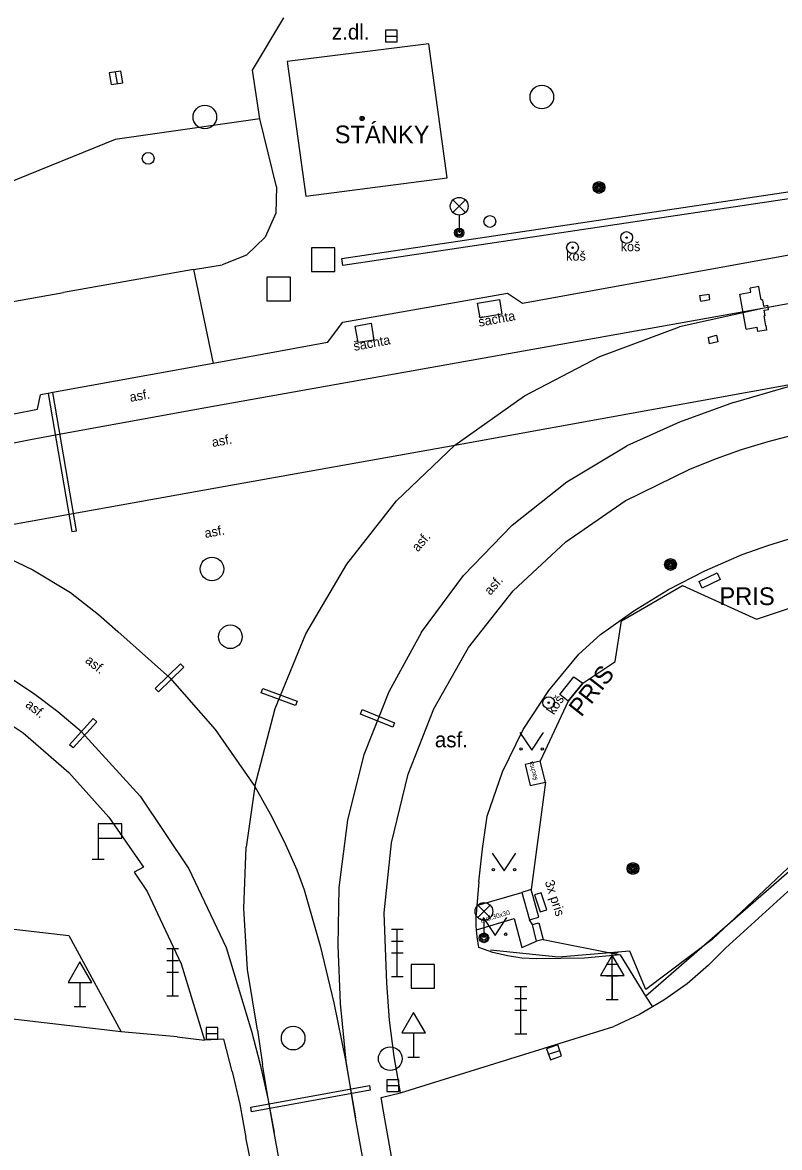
# Model space of a CAD drawing. Extents: x -600309 to -598967, y -1161267 to -1160292.
# Drawn here: x -599253.56 to -599221.51, y -1161223.69 to -1161176.07 of the extents above; entities that cross this region are included whole.
import ezdxf

# ---------------------------------------------------------------- set-up
doc = ezdxf.new("R2010")
doc.units = 0
for name, color, linetype in [('Level 10', 7, 'Continuous'), ('Level 11', 7, 'Continuous'), ('Level 13', 7, 'Continuous'), ('Level 23', 7, 'Continuous'), ('Level 24', 7, 'Continuous'), ('Level 25', 7, 'Continuous'), ('Level 26', 7, 'Continuous'), ('Level 27', 7, 'Continuous'), ('Level 28', 7, 'Continuous'), ('Level 33', 7, 'Continuous'), ('Level 34', 7, 'Continuous'), ('Level 36', 7, 'Continuous'), ('Level 39', 7, 'Continuous'), ('Level 40', 7, 'Continuous'), ('Level 41', 7, 'Continuous'), ('Level 42', 7, 'Continuous'), ('Level 5', 7, 'Continuous'), ('Level 9', 7, 'Continuous')]:
    doc.layers.add(name, color=color, linetype=linetype)

msp = doc.modelspace()

# ---------------------------------------------------------------- linework, layer by layer
at = {"layer": 'Level 10'}
for points in [[(-599243.51, -1161180.14), (-599243.82, -1161178.09), (-599242.49, -1161175.87)], [(-599243.51, -1161180.15), (-599249.64, -1161181.02), (-599254.23, -1161182.89)], [(-599232.39, -1161187.95), (-599216.66, -1161185.1)], [(-599240.64, -1161189.62), (-599239.99, -1161188.75), (-599233.02, -1161187.52), (-599232.39, -1161187.95)], [(-599240.64, -1161189.62), (-599245.49, -1161190.5)], [(-599245.49, -1161190.5), (-599252.28, -1161191.73), (-599252.48, -1161191.77), (-599252.8, -1161191.83)], [(-599225.3, -1161194.98), (-599224.21, -1161194.54), (-599223.11, -1161194.14), (-599221.98, -1161193.8), (-599220.85, -1161193.51)], [(-599234.68, -1161202.52), (-599232.78, -1161200.13), (-599230.55, -1161198.05), (-599228.04, -1161196.32), (-599225.3, -1161194.98)], [(-599238.14, -1161216.74), (-599238.24, -1161213.76), (-599237.94, -1161210.79), (-599237.23, -1161207.89), (-599236.14, -1161205.12), (-599234.68, -1161202.52)], [(-599255.66, -1161204.72), (-599253.54, -1161206.14), (-599251.6, -1161207.81), (-599249.9, -1161209.71), (-599248.44, -1161211.82)], [(-599248.44, -1161211.82), (-599248.83, -1161212.04)], [(-599248.83, -1161212.04), (-599248.29, -1161212.85), (-599246.84, -1161215.91), (-599245.86, -1161219.14)], [(-599223.79, -1161215.25), (-599220.07, -1161211.86)], [(-599224.51, -1161215.97), (-599223.79, -1161215.25)], [(-599249.38, -1161218.79), (-599256.77, -1161217.93), (-599271.44, -1161216.15)], [(-599224.51, -1161215.97), (-599225.42, -1161216.76), (-599226.4, -1161217.45), (-599226.88, -1161217.73), (-599227.43, -1161218.06), (-599228.52, -1161218.57)], [(-599237.56, -1161221.38), (-599237.83, -1161219.84), (-599238.02, -1161218.3), (-599238.14, -1161216.74)], [(-599247.01, -1161219.01), (-599249.38, -1161218.79)], [(-599237.56, -1161221.38), (-599228.52, -1161218.57)], [(-599247.01, -1161219.01), (-599245.86, -1161219.14)]]:
    msp.add_lwpolyline(points, dxfattribs=at)
at = {"layer": 'Level 11'}
for points in [[(-599242.81, -1161183.03), (-599243.51, -1161180.15), (-599243.51, -1161180.14)], [(-599242.81, -1161183.03), (-599242.83, -1161184.14), (-599243.28, -1161185.15), (-599244.08, -1161185.92), (-599245.11, -1161186.32)], [(-599246.32, -1161186.52), (-599245.11, -1161186.32)], [(-599246.32, -1161186.52), (-599251.83, -1161187.5)], [(-599246.32, -1161186.52), (-599245.49, -1161190.5)], [(-599222.38, -1161187.24), (-599222.75, -1161187.31)], [(-599222.72, -1161187.48), (-599222.75, -1161187.31)], [(-599222.35, -1161187.42), (-599222.38, -1161187.24)], [(-599285.55, -1161193.76), (-599281.38, -1161192.76), (-599251.83, -1161187.5)], [(-599224.88, -1161187.63), (-599224.49, -1161187.57)], [(-599224.83, -1161187.86), (-599224.88, -1161187.63)], [(-599224.83, -1161187.86), (-599224.45, -1161187.8)], [(-599224.45, -1161187.8), (-599224.49, -1161187.57)], [(-599223.19, -1161187.57), (-599222.72, -1161187.48)], [(-599222.92, -1161189.05), (-599223.19, -1161187.57)], [(-599222.28, -1161187.81), (-599222.35, -1161187.42)], [(-599222.23, -1161187.81), (-599222.28, -1161187.81)], [(-599222.23, -1161187.81), (-599222.18, -1161188.07)], [(-599222.18, -1161188.07), (-599222, -1161188.03)], [(-599222.15, -1161188.24), (-599221.97, -1161188.21)], [(-599222.11, -1161188.48), (-599222.15, -1161188.24)], [(-599221.97, -1161188.21), (-599222, -1161188.03)], [(-599222.11, -1161188.48), (-599222.16, -1161188.49)], [(-599222.08, -1161188.9), (-599222.09, -1161188.91), (-599222.16, -1161188.49)], [(-599222.92, -1161189.05), (-599222.47, -1161188.97)], [(-599222.47, -1161188.97), (-599222.44, -1161189.15)], [(-599222.05, -1161189.09), (-599222.44, -1161189.15)], [(-599222.08, -1161188.9), (-599222.05, -1161189.09)], [(-599224.53, -1161189.4), (-599224.17, -1161189.31)], [(-599224.53, -1161189.4), (-599224.48, -1161189.67)], [(-599224.12, -1161189.58), (-599224.48, -1161189.67)], [(-599224.17, -1161189.31), (-599224.12, -1161189.58)], [(-599252.93, -1161192.44), (-599252.8, -1161191.83)], [(-599262.96, -1161194.41), (-599252.93, -1161192.44)], [(-599223.08, -1161198.59), (-599222, -1161198.21), (-599220.91, -1161197.87), (-599219.8, -1161197.59), (-599218.68, -1161197.36)], [(-599229.09, -1161201.97), (-599227.68, -1161200.97), (-599226.2, -1161200.07), (-599224.67, -1161199.28), (-599223.08, -1161198.59)], [(-599230.01, -1161202.81), (-599229.09, -1161201.97)], [(-599233.88, -1161209.66), (-599233.23, -1161207.79), (-599232.36, -1161206), (-599231.28, -1161204.34), (-599230.01, -1161202.81)], [(-599227.18, -1161217.29), (-599220.44, -1161211.43), (-599216.22, -1161207.91)], [(-599234.24, -1161212.44), (-599234.08, -1161211.05), (-599233.88, -1161209.66)], [(-599234.24, -1161212.44), (-599234.32, -1161213.44), (-599234.35, -1161213.84)], [(-599234.32, -1161213.44), (-599232.42, -1161212.89)], [(-599257.7199, -1161214.01), (-599251.6, -1161214.7199), (-599249.38, -1161218.79)], [(-599234.24, -1161215.23), (-599234.31, -1161214.77), (-599234.34, -1161214.47), (-599234.35, -1161214.31), (-599234.35, -1161213.84)], [(-599234.34, -1161214.47), (-599232.74, -1161214), (-599232.41, -1161215.22), (-599231.8, -1161214.96)], [(-599231.97, -1161214.25), (-599232.09, -1161214.05)], [(-599231.78, -1161215.7), (-599232.41, -1161215.67), (-599233.03, -1161215.58), (-599233.64, -1161215.43), (-599234.24, -1161215.23)], [(-599228.25, -1161215.54), (-599229.77, -1161215.67), (-599231.78, -1161215.7)], [(-599228.25, -1161215.54), (-599227.18, -1161217.29)], [(-599227.18, -1161217.29), (-599226.88, -1161217.73)], [(-599244.68, -1161220.47), (-599245.04, -1161219.1), (-599245.86, -1161219.14)], [(-599244.68, -1161220.47), (-599244.36, -1161221.86), (-599244.1, -1161223.27)], [(-599236.75, -1161230.76), (-599238.26, -1161222.23), (-599238.38, -1161221.57), (-599237.56, -1161221.38)], [(-599242.28, -1161232.13), (-599244.1, -1161223.27)]]:
    msp.add_lwpolyline(points, dxfattribs=at)
at = {"layer": 'Level 13'}
for points in [[(-599176.03, -1161179.84), (-599185.38, -1161181.48), (-599211.11, -1161186.14), (-599222.22, -1161188.17), (-599231.95, -1161189.91), (-599245.73, -1161192.37), (-599252.16, -1161193.54), (-599253.22, -1161193.73), (-599269.67, -1161197)], [(-599254.02, -1161197.32), (-599251.59, -1161196.88), (-599245.38, -1161195.76), (-599235.26, -1161193.96), (-599218.74, -1161190.97), (-599212.41, -1161189.82), (-599183.76, -1161184.68), (-599173.82, -1161182.81)], [(-599222.22, -1161188.17), (-599225.74, -1161188.95)], [(-599235.26, -1161193.96), (-599232.31, -1161191.87), (-599229.12, -1161190.2), (-599225.74, -1161188.95)], [(-599223.46, -1161192.15), (-599221.12, -1161191.47), (-599218.74, -1161190.97)], [(-599223.46, -1161192.15), (-599225.74, -1161192.99)], [(-599225.74, -1161192.99), (-599227.97, -1161193.99)], [(-599243.72, -1161208.41), (-599242.86, -1161205.11), (-599241.56, -1161201.95), (-599239.83, -1161199), (-599237.72, -1161196.32), (-599235.26, -1161193.96)], [(-599236.66, -1161201.87), (-599234.89, -1161199.48), (-599232.83, -1161197.35), (-599230.51, -1161195.51), (-599227.97, -1161193.99)], [(-599256.29, -1161197.73), (-599253.12, -1161199.24), (-599251.53, -1161200.2), (-599250.35, -1161201.13), (-599249.52, -1161201.85)], [(-599268.01, -1161200.11), (-599266.08, -1161200.07), (-599263.89, -1161200.31), (-599261.69, -1161200.69), (-599259.15, -1161201.36), (-599257.24, -1161202.13), (-599255.3, -1161203.08), (-599254.18, -1161203.74), (-599253.1, -1161204.46), (-599252.06, -1161205.24), (-599251.07, -1161206.08)], [(-599249.52, -1161201.85), (-599247.33, -1161203.81), (-599245.4, -1161206), (-599243.73, -1161208.41)], [(-599240.15, -1161212.69), (-599239.79, -1161209.84), (-599239.09, -1161207.06), (-599238.03, -1161204.39), (-599236.65, -1161201.86)], [(-599251.07, -1161206.09), (-599248.58, -1161208.82), (-599246.52, -1161211.89), (-599244.94, -1161215.23)], [(-599243.73, -1161208.41), (-599244.09, -1161210.98)], [(-599243.72, -1161208.41), (-599243.07, -1161209.56)], [(-599243.07, -1161209.56), (-599242.48, -1161210.74), (-599241.95, -1161211.94)], [(-599243.61, -1161218.72), (-599244.03, -1161216.16), (-599244.19, -1161213.57), (-599244.09, -1161210.98)], [(-599241.95, -1161211.94), (-599241.63, -1161212.78)], [(-599241.63, -1161212.78), (-599240.96, -1161215.16), (-599240.38, -1161217.57), (-599239.88, -1161220), (-599239.46, -1161222.44)], [(-599239.46, -1161222.44), (-599239.85, -1161220.03), (-599240.1, -1161217.59), (-599240.2, -1161215.14), (-599240.15, -1161212.69)], [(-599244.94, -1161215.23), (-599243.87, -1161218.77)], [(-599243.87, -1161218.77), (-599243.5, -1161220.18), (-599243.17, -1161221.61), (-599242.9, -1161223.06)], [(-599243.61, -1161218.72), (-599243.4, -1161220.17)], [(-599242.9, -1161223.05), (-599243.16, -1161221.61), (-599243.4, -1161220.17)], [(-599238.11, -1161229.91), (-599239.46, -1161222.44)], [(-599241.55, -1161230.45), (-599242.9, -1161223.05)]]:
    msp.add_lwpolyline(points, dxfattribs=at)
at = {"layer": 'Level 23'}
for points in [[(-599225.61, -1161199.9), (-599222.48, -1161201.33), (-599202.67, -1161194.75), (-599197.63, -1161193.92), (-599196.7, -1161196.51)], [(-599228.2, -1161201.4), (-599225.61, -1161199.9)], [(-599228.46, -1161203.12), (-599228.2, -1161201.4)], [(-599230.45, -1161204.8), (-599229.84, -1161204.03), (-599228.52, -1161203.16), (-599228.46, -1161203.12)], [(-599230.45, -1161204.8), (-599231.64, -1161207.33)], [(-599231.42, -1161208.23), (-599232.02, -1161212.77)], [(-599231.52, -1161214.89), (-599228.25, -1161215.54)]]:
    msp.add_lwpolyline(points, dxfattribs=at)
at = {"layer": 'Level 24'}
for points in [[(-599240.04, -1161186.06), (-599216.7, -1161182.57)], [(-599216.66, -1161182.87), (-599240, -1161186.36)], [(-599240, -1161186.36), (-599240.04, -1161186.06)], [(-599251.27, -1161197.59), (-599252.28, -1161191.73), (-599252.48, -1161191.77)], [(-599252.48, -1161191.77), (-599251.47, -1161197.62)], [(-599251.47, -1161197.62), (-599251.27, -1161197.59)], [(-599224.91, -1161199.73), (-599224.15, -1161199.37)], [(-599224.78, -1161200.01), (-599224.91, -1161199.73)], [(-599224.02, -1161199.65), (-599224.78, -1161200.01)], [(-599224.15, -1161199.37), (-599224.02, -1161199.65)], [(-599247.94, -1161204.26), (-599246.87, -1161203.21)], [(-599246.73, -1161203.35), (-599247.81, -1161204.4)], [(-599246.87, -1161203.21), (-599246.73, -1161203.35)], [(-599230.81, -1161204.52), (-599230.22, -1161203.77)], [(-599229.84, -1161204.03), (-599230.45, -1161204.8)], [(-599230.22, -1161203.77), (-599229.84, -1161204.03)], [(-599247.81, -1161204.4), (-599247.94, -1161204.26)], [(-599243.45, -1161204.45), (-599243.39, -1161204.26)], [(-599242, -1161204.98), (-599243.45, -1161204.45)], [(-599243.39, -1161204.26), (-599241.93, -1161204.79)], [(-599230.45, -1161204.8), (-599230.81, -1161204.52)], [(-599241.93, -1161204.79), (-599242, -1161204.98)], [(-599239.25, -1161205.34), (-599239.18, -1161205.15)], [(-599237.88, -1161205.9), (-599239.25, -1161205.34)], [(-599239.18, -1161205.15), (-599237.81, -1161205.71)], [(-599251.57, -1161206.64), (-599250.57, -1161205.53)], [(-599250.42, -1161205.67), (-599251.42, -1161206.77)], [(-599250.57, -1161205.53), (-599250.42, -1161205.67)], [(-599237.81, -1161205.71), (-599237.88, -1161205.9)], [(-599251.42, -1161206.77), (-599251.57, -1161206.64)], [(-599231.6, -1161212.91), (-599231.88, -1161213)], [(-599231.88, -1161213), (-599231.64, -1161213.72)], [(-599231.36, -1161213.63), (-599231.6, -1161212.91)], [(-599231.64, -1161213.72), (-599231.36, -1161213.63)], [(-599243.9, -1161221.98), (-599238.87, -1161221.06)], [(-599238.87, -1161221.06), (-599238.84, -1161221.26)], [(-599238.84, -1161221.26), (-599243.87, -1161222.18)], [(-599243.87, -1161222.18), (-599243.9, -1161221.98)]]:
    msp.add_lwpolyline(points, dxfattribs=at)
at = {"layer": 'Level 25'}
for centre, radius in [((-599229.15, -1161183.05), 0.25), ((-599229.15, -1161183.05), 0.2), ((-599229.15, -1161183.05), 0.15), ((-599229.15, -1161183.05), 0.1), ((-599229.15, -1161183.05), 0.05), ((-599227.98, -1161185.17), 0.25), ((-599230.27, -1161185.6), 0.25), ((-599227.98, -1161185.17), 0.0303), ((-599230.27, -1161185.6), 0.0303), ((-599226.12, -1161199.01), 0.25), ((-599226.12, -1161199.01), 0.2), ((-599226.12, -1161199.01), 0.15), ((-599226.12, -1161199.01), 0.1), ((-599226.12, -1161199.01), 0.05), ((-599231.28, -1161204.86), 0.25), ((-599231.28, -1161204.86), 0.0303), ((-599227.71, -1161211.88), 0.25), ((-599227.71, -1161211.88), 0.2), ((-599227.71, -1161211.88), 0.15), ((-599227.71, -1161211.88), 0.1), ((-599227.71, -1161211.88), 0.05)]:
    msp.add_circle(centre, radius, dxfattribs=at)
at = {"layer": 'Level 26'}
for points in [[(-599241.33, -1161186.61), (-599240.33, -1161186.61), (-599240.33, -1161185.61), (-599241.33, -1161185.61)], [(-599243.22, -1161187.85), (-599242.22, -1161187.85), (-599242.22, -1161186.85), (-599243.22, -1161186.85)], [(-599237.11, -1161216.95), (-599236.11, -1161216.95), (-599236.11, -1161215.95), (-599237.11, -1161215.95)]]:
    msp.add_lwpolyline(points, close=True, dxfattribs=at)
for points in [[(-599234.29, -1161187.95), (-599233.36, -1161187.79)], [(-599233.36, -1161187.79), (-599233.26, -1161188.41)], [(-599234.18, -1161188.57), (-599234.29, -1161187.95)], [(-599239.47, -1161188.92), (-599238.8, -1161188.8)], [(-599238.8, -1161188.8), (-599238.68, -1161189.51)], [(-599233.26, -1161188.41), (-599234.18, -1161188.57)], [(-599239.35, -1161189.62), (-599239.47, -1161188.92)], [(-599238.68, -1161189.51), (-599239.35, -1161189.62)], [(-599231.64, -1161207.33), (-599232.27, -1161207.48)], [(-599231.42, -1161208.23), (-599231.64, -1161207.33)], [(-599232.27, -1161207.48), (-599232.06, -1161208.36)], [(-599232.06, -1161208.36), (-599231.42, -1161208.23)], [(-599232.02, -1161212.77), (-599232.42, -1161212.89)], [(-599232.42, -1161212.89), (-599232.09, -1161214.05)], [(-599231.69, -1161213.94), (-599232.02, -1161212.77)], [(-599232.09, -1161214.05), (-599231.69, -1161213.94)], [(-599231.97, -1161214.25), (-599231.69, -1161214.18)], [(-599231.8, -1161214.96), (-599231.97, -1161214.25)], [(-599231.69, -1161214.18), (-599231.52, -1161214.89)], [(-599231.52, -1161214.89), (-599231.8, -1161214.96)]]:
    msp.add_lwpolyline(points, dxfattribs=at)
at = {"layer": 'Level 27'}
for p, q in [((-599238.19, -1161176.64), (-599237.69, -1161176.64)), ((-599249.64, -1161178.1631), (-599249.56, -1161178.6567)), ((-599245.79, -1161218.86), (-599245.29, -1161218.86)), ((-599231.2859, -1161219.7428), (-599230.8141, -1161219.5772)), ((-599238.13, -1161221.07), (-599237.63, -1161221.07))]:
    msp.add_line(p, q, dxfattribs=at)
for points in [[(-599238.19, -1161176.89), (-599237.69, -1161176.89), (-599237.69, -1161176.39), (-599238.19, -1161176.39)], [(-599249.8868, -1161178.2031), (-599249.8068, -1161178.6967), (-599249.3132, -1161178.6167), (-599249.3932, -1161178.1231)], [(-599245.79, -1161219.11), (-599245.29, -1161219.11), (-599245.29, -1161218.61), (-599245.79, -1161218.61)], [(-599231.2031, -1161219.9787), (-599230.7313, -1161219.8131), (-599230.8969, -1161219.3413), (-599231.3687, -1161219.5069)], [(-599238.13, -1161221.32), (-599237.63, -1161221.32), (-599237.63, -1161220.82), (-599238.13, -1161220.82)]]:
    msp.add_lwpolyline(points, close=True, dxfattribs=at)
for centre in [(-599231.57, -1161179.22), (-599245.84, -1161180.07), (-599245.54, -1161199.2), (-599244.76, -1161202.07), (-599242.1, -1161219.06), (-599237.99, -1161219.93)]:
    msp.add_circle(centre, 0.5, dxfattribs=at)
at = {"layer": 'Level 28'}
for centre in [(-599248.24, -1161181.82), (-599233.77, -1161184.49)]:
    msp.add_circle(centre, 0.25, dxfattribs=at)
at = {"layer": 'Level 33'}
for p, q in [((-599235.335, -1161184.11), (-599234.805, -1161183.58)), ((-599235.335, -1161183.58), (-599234.805, -1161184.11)), ((-599235.07, -1161184.22), (-599235.07, -1161184.97)), ((-599234.285, -1161213.96), (-599233.755, -1161213.43)), ((-599234.285, -1161213.43), (-599233.755, -1161213.96)), ((-599237.94, -1161214.45), (-599237.44, -1161214.45)), ((-599237.69, -1161216.45), (-599237.69, -1161214.45)), ((-599234.02, -1161214.07), (-599234.02, -1161214.82)), ((-599237.94, -1161214.95), (-599237.44, -1161214.95)), ((-599247.45, -1161215.27), (-599246.95, -1161215.27)), ((-599247.2, -1161217.27), (-599247.2, -1161215.27)), ((-599237.94, -1161215.45), (-599237.44, -1161215.45)), ((-599228.84, -1161215.43), (-599228.34, -1161215.43)), ((-599228.59, -1161217.43), (-599228.59, -1161215.43)), ((-599247.45, -1161215.77), (-599246.95, -1161215.77)), ((-599228.84, -1161215.93), (-599228.34, -1161215.93)), ((-599247.45, -1161216.27), (-599246.95, -1161216.27)), ((-599228.84, -1161216.43), (-599228.34, -1161216.43)), ((-599237.94, -1161216.45), (-599237.44, -1161216.45)), ((-599232.71, -1161216.88), (-599232.21, -1161216.88)), ((-599232.46, -1161218.88), (-599232.46, -1161216.88)), ((-599247.45, -1161217.27), (-599246.95, -1161217.27)), ((-599232.71, -1161217.38), (-599232.21, -1161217.38)), ((-599228.84, -1161217.43), (-599228.34, -1161217.43)), ((-599232.71, -1161217.88), (-599232.21, -1161217.88)), ((-599232.71, -1161218.88), (-599232.21, -1161218.88))]:
    msp.add_line(p, q, dxfattribs=at)
for centre, radius in [((-599235.07, -1161183.845), 0.375), ((-599235.07, -1161184.97), 0.2), ((-599235.07, -1161184.97), 0.1445), ((-599235.07, -1161184.97), 0.0876), ((-599234.02, -1161213.695), 0.375), ((-599234.02, -1161214.82), 0.2), ((-599234.02, -1161214.82), 0.1445), ((-599234.02, -1161214.82), 0.0876)]:
    msp.add_circle(centre, radius, dxfattribs=at)
at = {"layer": 'Level 34'}
for p, q in [((-599250.36, -1161210.59), (-599250.36, -1161211.49)), ((-599250.61, -1161211.49), (-599250.11, -1161211.49)), ((-599228.59, -1161216.412), (-599228.59, -1161217.43)), ((-599251.13, -1161216.702), (-599251.13, -1161217.72)), ((-599251.38, -1161217.72), (-599250.88, -1161217.72)), ((-599237, -1161218.842), (-599237, -1161219.86)), ((-599237.25, -1161219.86), (-599236.75, -1161219.86))]:
    msp.add_line(p, q, dxfattribs=at)
for points in [[(-599250.36, -1161210.59), (-599249.36, -1161210.59), (-599249.36, -1161209.99), (-599250.36, -1161209.99)], [(-599251.63, -1161216.702), (-599250.63, -1161216.702), (-599251.13, -1161215.836)], [(-599229.09, -1161216.412), (-599228.09, -1161216.412), (-599228.59, -1161215.546)], [(-599237.5, -1161218.842), (-599236.5, -1161218.842), (-599237, -1161217.976)]]:
    msp.add_lwpolyline(points, close=True, dxfattribs=at)
at = {"layer": 'Level 36'}
for points in [[(-599232.5, -1161206.12), (-599232, -1161206.87), (-599231.5, -1161206.12)], [(-599233.67, -1161211.23), (-599233.17, -1161211.98), (-599232.67, -1161211.23)], [(-599234.05, -1161213.96), (-599233.55, -1161214.71), (-599233.05, -1161213.96)]]:
    msp.add_lwpolyline(points, dxfattribs=at)
for centre in [(-599232.4502, -1161206.8198), (-599231.5508, -1161206.8198), (-599233.6202, -1161211.9298), (-599232.7208, -1161211.9298), (-599234.0002, -1161214.6598), (-599233.1008, -1161214.6598)]:
    msp.add_circle(centre, 0.05, dxfattribs=at)
at = {"layer": 'Level 39'}
for radius in [0.09, 0.0398]:
    msp.add_circle((-599239.18, -1161180.13), radius, dxfattribs=at)
at = {"layer": 'Level 5'}
for points in [[(-599236.36, -1161176.9699), (-599242.35, -1161177.7199)], [(-599235.58, -1161182.65), (-599236.36, -1161176.9699)], [(-599242.35, -1161177.7199), (-599241.57, -1161183.42)], [(-599241.57, -1161183.42), (-599235.58, -1161182.65)]]:
    msp.add_lwpolyline(points, dxfattribs=at)
at = {"layer": 'Level 9'}
for points in [[(-599220.66, -1161211.4), (-599224.36, -1161214.89), (-599227.16, -1161217)], [(-599227.85, -1161215.38), (-599230.86, -1161215.64), (-599233.74, -1161215.34)], [(-599227.16, -1161217), (-599227.85, -1161215.38)]]:
    msp.add_lwpolyline(points, dxfattribs=at)

# ---------------------------------------------------------------- texts
at = {"layer": 'Level 40'}
for s, p in [('z.dl.', (-599240.46, -1161176.79)), ('asf.', (-599236.1, -1161206.75))]:
    msp.add_text(s, height=0.65, dxfattribs=at).set_placement(p)
for s, height, rotation, p in [('asf.', 0.4, 10.06865, (-599248.99, -1161192.13)), ('asf.', 0.4, 10.06865, (-599245.51, -1161194.04)), ('asf.', 0.4, 10.06865, (-599245.82, -1161197.89)), ('asf.', 0.4, 49.06812, (-599236.82, -1161198.5)), ('asf.', 0.4, 49.06812, (-599233.75, -1161200.34)), ('asf.', 0.4, 321.18922, (-599250.94, -1161203.13)), ('asf.', 0.4, 321.18922, (-599253.47, -1161205)), ('šachta', 0.2, 104, (-599231.75, -1161208.12)), ('3x pris', 0.4, 288, (-599231.45, -1161212.44)), ('b.dl.30x30', 0.2, 16, (-599234.13, -1161214.18))]:
    msp.add_text(s, height=height, rotation=rotation, dxfattribs=at).set_placement(p)
at = {"layer": 'Level 41'}
for s, p in [('STÁNKY', (-599240.34, -1161181.18)), ('PRIS', (-599224.05, -1161200.73))]:
    msp.add_text(s, height=0.75, dxfattribs=at).set_placement(p)
msp.add_text('PRIS', height=0.75, rotation=52, dxfattribs=at).set_placement((-599229.9, -1161205.5))
at = {"layer": 'Level 42'}
for p in [(-599228.23, -1161185.75), (-599230.54, -1161186.15)]:
    msp.add_text('koš', height=0.4, dxfattribs=at).set_placement(p)
for s, rotation, p in [('šachta', 10.47735, (-599234.22, -1161188.95)), ('šachta', 10.47735, (-599239.51, -1161189.97)), ('koš', 57, (-599231.06, -1161205.4))]:
    msp.add_text(s, height=0.4, rotation=rotation, dxfattribs=at).set_placement(p)

doc.saveas('drawing.dxf')
